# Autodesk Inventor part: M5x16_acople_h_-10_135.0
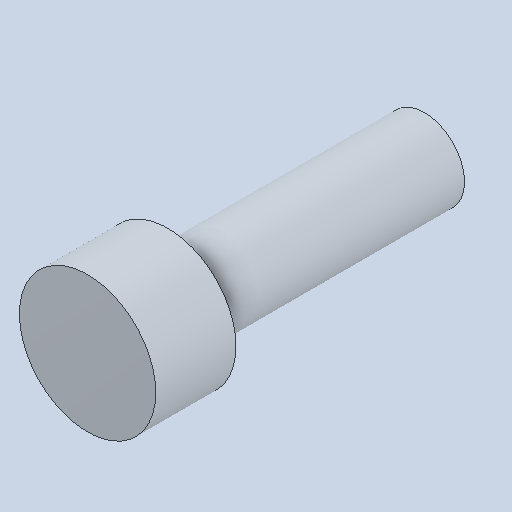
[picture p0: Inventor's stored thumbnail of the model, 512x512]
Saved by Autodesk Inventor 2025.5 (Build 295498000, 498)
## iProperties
Created: 2026-10
Part Number: M5x16_acople_h_-10_135.0
Material: Genérico
Document SubType Name: Modeling
Designer: Luis M
Density: 1 g/cm^3
Appearance: Valor por defecto
Author: Luis M
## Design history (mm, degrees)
feature "Base1"
node "Sólido1"
